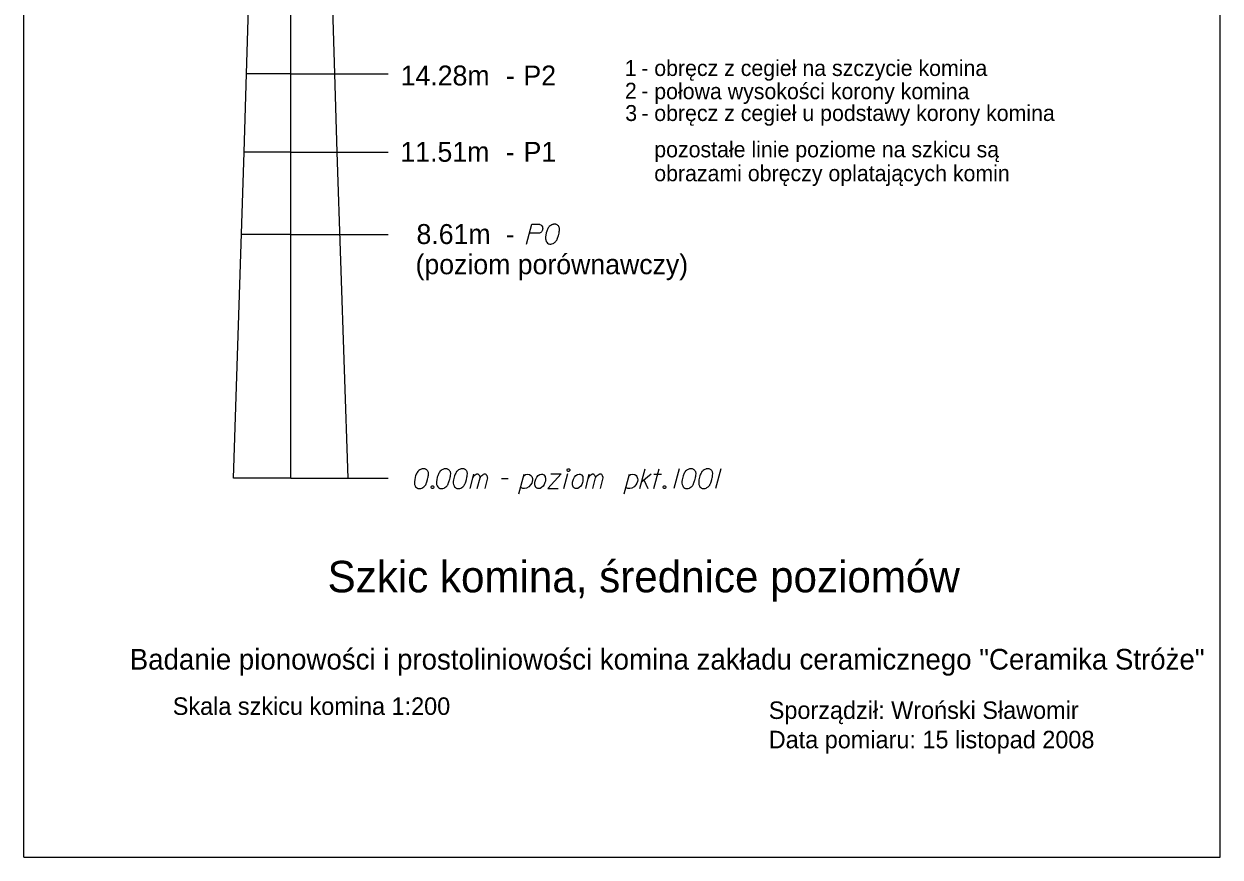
# Model space of a CAD drawing. Extents: x 138 to 6653, y -177 to 1520.
# Drawn here: x 167.3 to 188.3, y -30.54 to -15.91 of the extents above; entities that cross this region are included whole.
import ezdxf

# ---------------------------------------------------------------- set-up
doc = ezdxf.new("R2010")
doc.units = 0
for name, color, linetype in [('Opisy', 7, 'Continuous'), ('Ramka do drukowania', 7, 'Continuous'), ('Standard', 7, 'Continuous')]:
    doc.layers.add(name, color=color, linetype=linetype)

msp = doc.modelspace()

# ---------------------------------------------------------------- linework, layer by layer
at = {"layer": 'Ramka do drukowania'}
for p, q in [((167.297, -30.544), (167.297, -0.844)), ((188.297, -30.544), (188.297, -0.844)), ((167.297, -30.544), (188.297, -30.544))]:
    msp.add_line(p, q, dxfattribs=at)
at = {"layer": 'Standard'}
for p, q in [((171.981, -23.89), (171.981, -3.806)), ((171.206, -16.784), (171.249, -15.416)), ((172.755, -16.784), (172.712, -15.416)), ((171.162, -18.159), (171.206, -16.784)), ((171.981, -16.784), (171.206, -16.784)), ((171.981, -16.784), (173.691, -16.784)), ((172.799, -18.159), (172.755, -16.784)), ((170.974, -23.89), (171.162, -18.159)), ((171.981, -18.159), (171.162, -18.159)), ((171.981, -18.159), (173.691, -18.159)), ((172.987, -23.89), (172.799, -18.159)), ((171.981, -19.605), (171.114, -19.605)), ((171.981, -19.605), (173.691, -19.605)), ((171.981, -23.89), (170.974, -23.89)), ((171.981, -23.89), (173.691, -23.89))]:
    msp.add_line(p, q, dxfattribs=at)
for points in [[(176.118, -19.774), (176.211, -19.424), (176.33, -19.424), (176.346, -19.427), (176.355, -19.43), (176.371, -19.438), (176.382, -19.446), (176.39, -19.457), (176.399, -19.471), (176.404, -19.49), (176.407, -19.507), (176.404, -19.521), (176.401, -19.532), (176.396, -19.543), (176.39, -19.551), (176.382, -19.562), (176.371, -19.57), (176.363, -19.576), (176.349, -19.581), (176.335, -19.584), (176.17, -19.584)], [(176.619, -19.424), (176.614, -19.424), (176.597, -19.427), (176.586, -19.43), (176.578, -19.433), (176.564, -19.438), (176.548, -19.446), (176.534, -19.455), (176.52, -19.466), (176.512, -19.477), (176.503, -19.49), (176.495, -19.504), (176.487, -19.521), (176.481, -19.532), (176.476, -19.548), (176.468, -19.576), (176.459, -19.617), (176.454, -19.65), (176.454, -19.681), (176.457, -19.703), (176.468, -19.727), (176.476, -19.741), (176.49, -19.758), (176.506, -19.769), (176.514, -19.772), (176.531, -19.774), (176.545, -19.774), (176.567, -19.772), (176.586, -19.766), (176.6, -19.758), (176.619, -19.744), (176.627, -19.736), (176.638, -19.725), (176.647, -19.714), (176.652, -19.705), (176.658, -19.692), (176.661, -19.686), (176.666, -19.672), (176.672, -19.656), (176.677, -19.639), (176.68, -19.628), (176.683, -19.62), (176.685, -19.609), (176.691, -19.584), (176.694, -19.57), (176.696, -19.557), (176.699, -19.537), (176.702, -19.513), (176.702, -19.504), (176.699, -19.493), (176.696, -19.482), (176.688, -19.466), (176.68, -19.455), (176.672, -19.446), (176.661, -19.438), (176.649, -19.433), (176.641, -19.43), (176.633, -19.427), (176.619, -19.424)], [(174.317, -23.721), (174.312, -23.721), (174.295, -23.724), (174.284, -23.726), (174.276, -23.729), (174.262, -23.735), (174.246, -23.743), (174.232, -23.751), (174.218, -23.762), (174.21, -23.773), (174.202, -23.787), (174.193, -23.801), (174.185, -23.817), (174.18, -23.828), (174.174, -23.845), (174.166, -23.872), (174.158, -23.914), (174.152, -23.947), (174.152, -23.977), (174.155, -23.999), (174.166, -24.024), (174.174, -24.038), (174.188, -24.054), (174.204, -24.065), (174.213, -24.068), (174.229, -24.071), (174.243, -24.071), (174.265, -24.068), (174.284, -24.062), (174.298, -24.054), (174.317, -24.04), (174.326, -24.032), (174.337, -24.021), (174.345, -24.01), (174.35, -24.002), (174.356, -23.988), (174.359, -23.983), (174.364, -23.969), (174.37, -23.952), (174.375, -23.936), (174.378, -23.925), (174.381, -23.916), (174.384, -23.905), (174.389, -23.881), (174.392, -23.867), (174.395, -23.853), (174.397, -23.834), (174.4, -23.809), (174.4, -23.801), (174.397, -23.79), (174.395, -23.779), (174.386, -23.762), (174.378, -23.751), (174.37, -23.743), (174.359, -23.735), (174.348, -23.729), (174.339, -23.726), (174.331, -23.724), (174.317, -23.721)], [(174.706, -23.721), (174.7, -23.721), (174.684, -23.724), (174.673, -23.726), (174.665, -23.729), (174.651, -23.735), (174.634, -23.743), (174.621, -23.751), (174.607, -23.762), (174.598, -23.773), (174.59, -23.787), (174.582, -23.801), (174.574, -23.817), (174.568, -23.828), (174.563, -23.845), (174.554, -23.872), (174.546, -23.914), (174.541, -23.947), (174.541, -23.977), (174.543, -23.999), (174.554, -24.024), (174.563, -24.038), (174.576, -24.054), (174.593, -24.065), (174.601, -24.068), (174.618, -24.071), (174.632, -24.071), (174.654, -24.068), (174.673, -24.062), (174.687, -24.054), (174.706, -24.04), (174.714, -24.032), (174.725, -24.021), (174.733, -24.01), (174.739, -24.002), (174.745, -23.988), (174.747, -23.983), (174.753, -23.969), (174.758, -23.952), (174.764, -23.936), (174.767, -23.925), (174.769, -23.916), (174.772, -23.905), (174.778, -23.881), (174.78, -23.867), (174.783, -23.853), (174.786, -23.834), (174.789, -23.809), (174.789, -23.801), (174.786, -23.79), (174.783, -23.779), (174.775, -23.762), (174.767, -23.751), (174.758, -23.743), (174.747, -23.735), (174.736, -23.729), (174.728, -23.726), (174.72, -23.724), (174.706, -23.721)], [(175.001, -23.721), (174.995, -23.721), (174.979, -23.724), (174.968, -23.726), (174.959, -23.729), (174.946, -23.735), (174.929, -23.743), (174.915, -23.751), (174.902, -23.762), (174.893, -23.773), (174.885, -23.787), (174.877, -23.801), (174.868, -23.817), (174.863, -23.828), (174.857, -23.845), (174.849, -23.872), (174.841, -23.914), (174.835, -23.947), (174.835, -23.977), (174.838, -23.999), (174.849, -24.024), (174.857, -24.038), (174.871, -24.054), (174.888, -24.065), (174.896, -24.068), (174.913, -24.071), (174.926, -24.071), (174.948, -24.068), (174.968, -24.062), (174.982, -24.054), (175.001, -24.04), (175.009, -24.032), (175.02, -24.021), (175.028, -24.01), (175.034, -24.002), (175.039, -23.988), (175.042, -23.983), (175.048, -23.969), (175.053, -23.952), (175.059, -23.936), (175.061, -23.925), (175.064, -23.916), (175.067, -23.905), (175.072, -23.881), (175.075, -23.867), (175.078, -23.853), (175.081, -23.834), (175.083, -23.809), (175.083, -23.801), (175.081, -23.79), (175.078, -23.779), (175.07, -23.762), (175.061, -23.751), (175.053, -23.743), (175.042, -23.735), (175.031, -23.729), (175.023, -23.726), (175.015, -23.724), (175.001, -23.721)], [(176.85, -23.721), (176.864, -23.721), (176.872, -23.726), (176.881, -23.737), (176.881, -23.751), (176.872, -23.762), (176.864, -23.768), (176.85, -23.768), (176.842, -23.762), (176.834, -23.751), (176.834, -23.737), (176.842, -23.726), (176.85, -23.721)], [(178.112, -24.071), (178.206, -23.721)], [(178.358, -24.071), (178.449, -23.721)], [(178.801, -23.721), (178.708, -24.071)], [(179.013, -23.721), (179.008, -23.721), (178.991, -23.724), (178.98, -23.726), (178.972, -23.729), (178.958, -23.735), (178.942, -23.743), (178.928, -23.751), (178.914, -23.762), (178.906, -23.773), (178.898, -23.787), (178.889, -23.801), (178.881, -23.817), (178.876, -23.828), (178.87, -23.845), (178.862, -23.872), (178.854, -23.914), (178.848, -23.947), (178.848, -23.977), (178.851, -23.999), (178.862, -24.024), (178.87, -24.038), (178.884, -24.054), (178.9, -24.065), (178.909, -24.068), (178.925, -24.071), (178.939, -24.071), (178.961, -24.068), (178.98, -24.062), (178.994, -24.054), (179.013, -24.04), (179.022, -24.032), (179.033, -24.021), (179.041, -24.01), (179.047, -24.002), (179.052, -23.988), (179.055, -23.983), (179.06, -23.969), (179.066, -23.952), (179.071, -23.936), (179.074, -23.925), (179.077, -23.916), (179.08, -23.905), (179.085, -23.881), (179.088, -23.867), (179.091, -23.853), (179.093, -23.834), (179.096, -23.809), (179.096, -23.801), (179.093, -23.79), (179.091, -23.779), (179.082, -23.762), (179.074, -23.751), (179.066, -23.743), (179.055, -23.735), (179.044, -23.729), (179.035, -23.726), (179.027, -23.724), (179.013, -23.721)], [(179.308, -23.721), (179.303, -23.721), (179.286, -23.724), (179.275, -23.726), (179.267, -23.729), (179.253, -23.735), (179.237, -23.743), (179.223, -23.751), (179.209, -23.762), (179.201, -23.773), (179.193, -23.787), (179.184, -23.801), (179.176, -23.817), (179.17, -23.828), (179.165, -23.845), (179.157, -23.872), (179.148, -23.914), (179.143, -23.947), (179.143, -23.977), (179.146, -23.999), (179.157, -24.024), (179.165, -24.038), (179.179, -24.054), (179.195, -24.065), (179.204, -24.068), (179.22, -24.071), (179.234, -24.071), (179.256, -24.068), (179.275, -24.062), (179.289, -24.054), (179.308, -24.04), (179.317, -24.032), (179.328, -24.021), (179.336, -24.01), (179.341, -24.002), (179.347, -23.988), (179.35, -23.983), (179.355, -23.969), (179.361, -23.952), (179.366, -23.936), (179.369, -23.925), (179.372, -23.916), (179.374, -23.905), (179.38, -23.881), (179.383, -23.867), (179.385, -23.853), (179.388, -23.834), (179.391, -23.809), (179.391, -23.801), (179.388, -23.79), (179.385, -23.779), (179.377, -23.762), (179.369, -23.751), (179.361, -23.743), (179.35, -23.735), (179.339, -23.729), (179.33, -23.726), (179.322, -23.724), (179.308, -23.721)], [(179.531, -23.721), (179.438, -24.071)], [(175.13, -24.071), (175.194, -23.82)], [(175.177, -23.886), (175.191, -23.856), (175.205, -23.839), (175.221, -23.828), (175.238, -23.82), (175.249, -23.814), (175.265, -23.814), (175.271, -23.817), (175.282, -23.828), (175.293, -23.842), (175.301, -23.867), (175.304, -23.881), (175.318, -23.856), (175.334, -23.839), (175.351, -23.828), (175.367, -23.82), (175.381, -23.814), (175.395, -23.814), (175.406, -23.817), (175.414, -23.828), (175.422, -23.842), (175.431, -23.867), (175.433, -23.881), (175.387, -24.071)], [(175.257, -24.071), (175.304, -23.881)], [(175.682, -23.894), (175.8, -23.894)], [(175.988, -24.162), (176.081, -23.817)], [(176.073, -23.847), (176.101, -23.825), (176.142, -23.817), (176.175, -23.823), (176.197, -23.839), (176.214, -23.861), (176.225, -23.892), (176.227, -23.919), (176.222, -23.944), (176.214, -23.974), (176.192, -24.007), (176.164, -24.038), (176.123, -24.065), (176.087, -24.071), (176.054, -24.068), (176.018, -24.049)], [(176.382, -23.817), (176.401, -23.817), (176.423, -23.828), (176.445, -23.859), (176.448, -23.872), (176.451, -23.886), (176.451, -23.897), (176.451, -23.938), (176.442, -23.966), (176.429, -23.999), (176.412, -24.027), (176.384, -24.051), (176.36, -24.071), (176.318, -24.071), (176.302, -24.065), (176.285, -24.051), (176.277, -24.038), (176.266, -24.005), (176.266, -23.955), (176.271, -23.938), (176.283, -23.903), (176.294, -23.883), (176.299, -23.872), (176.327, -23.842), (176.354, -23.825), (176.382, -23.817)], [(176.547, -23.812), (176.726, -23.812), (176.497, -24.071), (176.674, -24.071)], [(176.773, -24.071), (176.845, -23.803)], [(177.043, -23.817), (177.062, -23.817), (177.084, -23.828), (177.107, -23.859), (177.109, -23.872), (177.112, -23.886), (177.112, -23.897), (177.112, -23.938), (177.104, -23.966), (177.09, -23.999), (177.073, -24.027), (177.046, -24.051), (177.021, -24.071), (176.98, -24.071), (176.963, -24.065), (176.947, -24.051), (176.938, -24.038), (176.927, -24.005), (176.927, -23.955), (176.933, -23.938), (176.944, -23.903), (176.955, -23.883), (176.96, -23.872), (176.988, -23.842), (177.016, -23.825), (177.043, -23.817)], [(177.159, -24.071), (177.222, -23.82)], [(177.206, -23.886), (177.219, -23.856), (177.233, -23.839), (177.25, -23.828), (177.266, -23.82), (177.277, -23.814), (177.294, -23.814), (177.299, -23.817), (177.31, -23.828), (177.321, -23.842), (177.33, -23.867), (177.332, -23.881), (177.346, -23.856), (177.363, -23.839), (177.379, -23.828), (177.396, -23.82), (177.41, -23.814), (177.423, -23.814), (177.434, -23.817), (177.443, -23.828), (177.451, -23.842), (177.459, -23.867), (177.462, -23.881), (177.415, -24.071)], [(177.286, -24.071), (177.332, -23.881)], [(177.834, -24.162), (177.928, -23.817)], [(177.919, -23.847), (177.947, -23.825), (177.988, -23.817), (178.021, -23.823), (178.043, -23.839), (178.06, -23.861), (178.071, -23.892), (178.074, -23.919), (178.068, -23.944), (178.06, -23.974), (178.038, -24.007), (178.01, -24.038), (177.969, -24.065), (177.933, -24.071), (177.9, -24.068), (177.864, -24.049)], [(178.145, -23.947), (178.311, -23.809)], [(178.179, -23.919), (178.25, -24.071)], [(178.358, -23.817), (178.49, -23.817)], [(174.463, -24.024), (174.477, -24.024), (174.485, -24.029), (174.494, -24.04), (174.494, -24.054), (174.485, -24.065), (174.477, -24.071), (174.463, -24.071), (174.455, -24.065), (174.447, -24.054), (174.447, -24.04), (174.455, -24.029), (174.463, -24.024)], [(178.537, -24.024), (178.551, -24.024), (178.559, -24.029), (178.567, -24.04), (178.567, -24.054), (178.559, -24.065), (178.551, -24.071), (178.537, -24.071), (178.528, -24.065), (178.52, -24.054), (178.52, -24.04), (178.528, -24.029), (178.537, -24.024)]]:
    msp.add_lwpolyline(points, dxfattribs=at)

# ---------------------------------------------------------------- texts
at = {"layer": 'Opisy'}
msp.add_text('Data pomiaru: 15 listopad 2008', height=0.30766, dxfattribs=at).set_placement((180.373, -28.633))
at = {"layer": 'Standard'}
for s, height, p in [('1', 0.28, (177.845, -16.822)), ('obręcz z cegieł na szczycie komina', 0.27991, (178.363, -16.822)), ('14.28m', 0.35, (173.911, -16.989)), ('P2', 0.35, (176.067, -16.989)), ('-', 0.28, (178.136, -16.822)), ('-', 0.35, (175.758, -16.989)), ('2', 0.28, (177.848, -17.221)), ('połowa wysokości korony komina', 0.27991, (178.363, -17.23)), ('-', 0.28, (178.136, -17.221)), ('3', 0.28, (177.854, -17.613)), ('obręcz z cegieł u podstawy korony komina', 0.27991, (178.363, -17.613)), ('-', 0.28, (178.137, -17.613)), ('11.51m', 0.35, (173.907, -18.329)), ('P1', 0.35, (176.069, -18.329)), ('pozostałe linie poziome na szkicu są', 0.27991, (178.363, -18.251)), ('-', 0.35, (175.756, -18.329)), ('obrazami obręczy oplatających komin', 0.27991, (178.363, -18.671)), ('8.61m', 0.35, (174.189, -19.774)), ('-', 0.35, (175.756, -19.774)), ('(poziom porównawczy)', 0.35, (174.172, -20.305)), ('Szkic komina, średnice poziomów', 0.55314, (172.628, -25.893)), ('Badanie pionowości i prostoliniowości komina zakładu ceramicznego "Ceramika Stróże"', 0.36281, (169.155, -27.25)), ('Skala szkicu komina 1:200', 0.30766, (169.91, -28.046)), ('Sporządził: Wroński Sławomir', 0.30766, (180.373, -28.117))]:
    msp.add_text(s, height=height, dxfattribs=at).set_placement(p)

doc.saveas('drawing.dxf')
